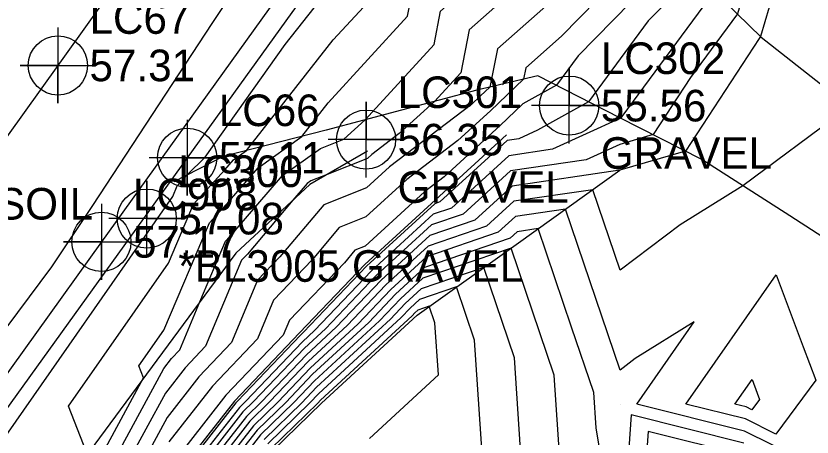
# Model space of a CAD drawing. Extents: x 2188792 to 2191981, y 386090 to 389710.
# Drawn here: x 2189752.4 to 2189815.5, y 387057.5 to 387090.8 of the extents above; entities that cross this region are included whole.
import ezdxf

# ---------------------------------------------------------------- set-up
doc = ezdxf.new("R2010")
doc.units = 0
for name, color, linetype in [('DTM Contours Major', 7, 'Continuous'), ('DTM Contours Minor', 7, 'Continuous'), ('Exist DTM QL2 LIDAR Elevation Point', 7, 'Continuous'), ('Exist Roads EOP', 7, 'Continuous'), ('Exist Roads EOP Cogo Elevation', 7, 'Continuous'), ('Exist Roads EOP Cogo Number', 7, 'Continuous'), ('Exist Roads EOP Cogo Point CELL', 7, 'Continuous'), ('Exist Roads EOT', 7, 'Continuous'), ('Exist Roads EOT Cogo Elevation', 7, 'Continuous'), ('Exist Roads EOT Cogo Number', 7, 'Continuous'), ('Exist Roads EOT Cogo Point CELL', 7, 'Continuous'), ('Exist Roads Soil Cogo Comment', 7, 'Continuous'), ('Exist Roads Soil Cogo Elevation', 7, 'Continuous'), ('Exist Roads Soil Cogo Number', 7, 'Continuous'), ('Exist Roads Soil Cogo Point CELL', 7, 'Continuous'), ('PH Exist DTM Breakline', 7, 'Continuous')]:
    doc.layers.add(name, color=color, linetype=linetype)

msp = doc.modelspace()

# ---------------------------------------------------------------- linework, layer by layer
at = {"layer": 'DTM Contours Major'}
for points in [[(2189750.977, 387056.76), (2189764.817, 387076.56), (2189765.17, 387077.392), (2189765.959, 387078.254), (2189767.371, 387079.663), (2189773.725, 387088.569), (2189777.916, 387093.909), (2189779.211, 387095.322), (2189779.288, 387095.712), (2189780.643, 387096.912), (2189782.512, 387099.089), (2189785.828, 387103.954), (2189796.579, 387119.177), (2189798.068, 387122.523), (2189798.475, 387123.446), (2189798.539, 387123.804), (2189808.292, 387137.215), (2189808.919, 387138.142), (2189809.222, 387138.615), (2189825.593, 387161.988)], [(2189818.014, 387135.578), (2189811.058, 387126.809), (2189810.786, 387125.379), (2189808.066, 387119.62), (2189806.017, 387115.841), (2189806.165, 387114.826), (2189804.371, 387109.683), (2189803.213, 387101.149), (2189803.472, 387100.716), (2189802.955, 387099.63), (2189799.965, 387096.58), (2189790.532, 387088.231), (2189789.941, 387085.204), (2189789.202, 387084.501), (2189788.475, 387083.836), (2189781.976, 387078.894), (2189780.172, 387077.246), (2189776.768, 387075.899), (2189773.29, 387071.764), (2189771.533, 387069.923), (2189769.466, 387064.988), (2189766.872, 387062.269), (2189764.365, 387059.07), (2189762.119, 387054.93)], [(2189818.839, 387129.976), (2189815.396, 387125.636), (2189814.426, 387120.529), (2189813.21, 387117.954), (2189812.294, 387116.264), (2189812.789, 387112.864), (2189811.979, 387110.541), (2189811.456, 387106.687), (2189814.112, 387102.255), (2189810.785, 387095.259), (2189809.534, 387091.004), (2189805.828, 387085.965), (2189802.864, 387081.443), (2189800.235, 387080.671), (2189797.567, 387079.45), (2189791.562, 387078.572), (2189787.825, 387075.156), (2189785.311, 387074.293), (2189780.928, 387070.288), (2189776.899, 387066.066), (2189775.243, 387064.539), (2189771.214, 387060.317), (2189770.37, 387059.498), (2189766.477, 387054.529)], [(2189795.488, 387055.37), (2189795.02, 387062.414), (2189791.607, 387072.471), (2189784.63, 387070.077), (2189782.841, 387068.441), (2189781.195, 387066.717), (2189776.043, 387061.965), (2189774.397, 387060.241), (2189771.771, 387057.69), (2189770.182, 387055.661)], [(2189809.984, 387056.073), (2189802.473, 387057.954), (2189801.923, 387050.273)]]:
    msp.add_lwpolyline(points, dxfattribs=at)
at = {"layer": 'DTM Contours Minor'}
for points in [[(2189757.992, 387056.32), (2189756.554, 387059.949), (2189764.468, 387071.271), (2189766.445, 387075.932), (2189768.945, 387078.662), (2189769.622, 387079.446), (2189770.648, 387080.179), (2189777.522, 387088.937), (2189781.313, 387093.073), (2189781.536, 387094.216), (2189785.504, 387097.728), (2189790.975, 387104.101), (2189798.548, 387115.211), (2189798.708, 387116.016), (2189799.145, 387116.599), (2189801.574, 387122.107), (2189802.082, 387124.936), (2189808.645, 387133.96), (2189811.25, 387137.817), (2189812.51, 387139.785), (2189824.983, 387157.591)], [(2189809.4, 387152.406), (2189801.396, 387139.864), (2189794.846, 387131.758), (2189788.146, 387120.877), (2189781.876, 387111.472), (2189771.155, 387095.136), (2189767.896, 387090.241), (2189758.451, 387075.833), (2189755.214, 387070.994), (2189740.876, 387051.783), (2189738.057, 387047.608), (2189727.447, 387033.342), (2189723.289, 387027.488), (2189710.113, 387008.133), (2189707.688, 387004.715), (2189696.068, 386987.603)], [(2189759.151, 387055.997), (2189762.508, 387062.186), (2189762.131, 387063.138), (2189764.119, 387065.982), (2189767.721, 387074.471), (2189769.273, 387076.167), (2189771.567, 387078.822), (2189775.039, 387081.303), (2189777.128, 387083.965), (2189783.415, 387090.825), (2189783.785, 387092.72), (2189790.365, 387098.543), (2189799.439, 387109.114), (2189800.025, 387109.974), (2189801.185, 387115.826), (2189804.36, 387120.058), (2189804.673, 387120.768), (2189805.625, 387126.067), (2189808.999, 387130.705), (2189813.581, 387137.493), (2189815.799, 387140.954)], [(2189760.14, 387055.641), (2189764.093, 387062.926), (2189764.718, 387063.724), (2189765.365, 387064.402), (2189766.961, 387068.213), (2189768.996, 387073.01), (2189769.602, 387073.672), (2189773.512, 387078.197), (2189776.52, 387080.347), (2189778.363, 387081.081), (2189780.054, 387082.615), (2189785.517, 387088.576), (2189786.034, 387091.223), (2189795.226, 387099.359), (2189800.987, 387106.07), (2189801.449, 387109.537), (2189803.322, 387115.057), (2189803.515, 387115.61), (2189803.506, 387115.672), (2189806.008, 387120.286), (2189809.104, 387126.842), (2189809.169, 387127.199), (2189809.352, 387127.451), (2189815.912, 387137.168)], [(2189818.179, 387134.458), (2189811.925, 387126.574), (2189811.514, 387124.409), (2189809.095, 387119.286), (2189807.273, 387115.926), (2189807.49, 387114.433), (2189805.893, 387109.854), (2189804.861, 387102.256), (2189805.6, 387101.024), (2189804.127, 387097.927), (2189795.604, 387089.233), (2189792.781, 387086.735), (2189792.604, 387085.829), (2189789.977, 387083.329), (2189787.395, 387080.969), (2189783.365, 387077.905), (2189780.115, 387074.935), (2189778.004, 387074.1), (2189775.847, 387071.536), (2189772.799, 387068.341), (2189771.517, 387065.281), (2189767.949, 387061.541), (2189764.501, 387057.141)], [(2189818.344, 387133.337), (2189812.793, 387126.34), (2189812.242, 387123.439), (2189810.124, 387118.953), (2189808.528, 387116.01), (2189808.814, 387114.041), (2189807.414, 387110.026), (2189806.51, 387103.364), (2189807.728, 387101.332), (2189805.299, 387096.224), (2189796.921, 387087.678), (2189795.204, 387085.349), (2189792.554, 387083.871), (2189790.753, 387082.158), (2189786.315, 387078.103), (2189784.754, 387076.915), (2189780.058, 387072.624), (2189779.24, 387072.3), (2189778.405, 387071.307), (2189774.064, 387066.759), (2189773.568, 387065.573), (2189769.026, 387060.814), (2189764.637, 387055.213)], [(2189818.509, 387132.217), (2189813.661, 387126.105), (2189812.97, 387122.469), (2189811.153, 387118.62), (2189809.783, 387116.095), (2189810.139, 387113.649), (2189808.936, 387110.198), (2189808.158, 387104.472), (2189809.856, 387101.64), (2189806.471, 387094.521), (2189802.47, 387090.439), (2189797.757, 387084.047), (2189793.715, 387081.793), (2189792.226, 387081.112), (2189791.293, 387080.975), (2189785.973, 387076.114), (2189785.583, 387075.98), (2189780.162, 387071.027), (2189775.18, 387065.806), (2189774.923, 387065.569), (2189769.941, 387060.348), (2189769.81, 387060.221), (2189764.996, 387054.076)], [(2189818.674, 387131.097), (2189814.528, 387125.871), (2189813.698, 387121.499), (2189812.181, 387118.287), (2189811.039, 387116.18), (2189811.464, 387113.256), (2189810.457, 387110.37), (2189809.807, 387105.58), (2189811.984, 387101.948), (2189807.799, 387093.145), (2189807.7, 387092.809), (2189800.397, 387082.878), (2189800.311, 387082.745), (2189800.233, 387082.723), (2189794.896, 387080.281), (2189791.428, 387079.773), (2189786.899, 387075.635), (2189785.447, 387075.137), (2189780.545, 387070.658), (2189776.04, 387065.936), (2189775.083, 387065.054), (2189770.577, 387060.333), (2189770.09, 387059.859), (2189765.736, 387054.303)], [(2189816.264, 387125.402), (2189815.154, 387119.559), (2189814.239, 387117.621), (2189813.55, 387116.349), (2189814.114, 387112.471), (2189813.5, 387110.713), (2189813.104, 387107.795), (2189816.24, 387102.563), (2189813.772, 387097.372), (2189811.367, 387089.198), (2189811.259, 387089.052), (2189805.417, 387080.141), (2189800.237, 387078.62), (2189791.697, 387077.37), (2189788.75, 387074.677), (2189785.174, 387073.45), (2189781.31, 387069.919), (2189777.758, 387066.197), (2189775.403, 387064.024), (2189771.851, 387060.302), (2189770.65, 387059.136), (2189767.218, 387054.755)], [(2189800.087, 387100.175), (2189788.283, 387089.727), (2189787.62, 387086.327), (2189785.553, 387084.073), (2189782.747, 387081.526), (2189780.587, 387079.884), (2189780.229, 387079.557), (2189777.044, 387078.296), (2189775.747, 387077.78), (2189775.457, 387077.573), (2189774.325, 387076.263), (2189770.732, 387071.992), (2189770.268, 387071.506), (2189767.416, 387064.695), (2189765.795, 387062.997), (2189764.229, 387060.998), (2189761.129, 387055.285)], [(2189817.868, 387083.253), (2189809.959, 387077.399), (2189804.997, 387074.311), (2189800.241, 387070.715), (2189798.08, 387077.083), (2189791.832, 387076.168), (2189789.676, 387074.198), (2189785.038, 387072.607), (2189781.693, 387069.549), (2189778.617, 387066.327), (2189775.563, 387063.51), (2189772.487, 387060.287), (2189770.931, 387058.774), (2189767.959, 387054.982)], [(2189814.472, 387055.803), (2189810.108, 387057.987), (2189801.564, 387060.127), (2189806.106, 387066.618), (2189801.449, 387063.722), (2189800.244, 387062.81), (2189795.922, 387075.546), (2189791.967, 387074.967), (2189790.602, 387073.719), (2189784.902, 387071.763), (2189782.075, 387069.18), (2189779.477, 387066.457), (2189775.723, 387062.995), (2189773.124, 387060.272), (2189771.211, 387058.413), (2189768.7, 387055.208)], [(2189799.705, 387050.126), (2189798.353, 387058.234), (2189798.167, 387061.036), (2189796.411, 387066.211), (2189793.764, 387074.008), (2189792.101, 387073.765), (2189791.527, 387073.241), (2189784.766, 387070.92), (2189782.458, 387068.811), (2189780.336, 387066.587), (2189775.883, 387062.48), (2189773.761, 387060.256), (2189771.491, 387058.051), (2189769.441, 387055.435)], [(2189792.623, 387052.505), (2189791.873, 387063.791), (2189789.449, 387070.934), (2189784.494, 387069.233), (2189783.223, 387068.072), (2189782.055, 387066.847), (2189776.202, 387061.45), (2189775.034, 387060.226), (2189772.051, 387057.328)], [(2189810.17, 387058.944), (2189805.449, 387060.127), (2189812.608, 387070.36), (2189814.756, 387064.65), (2189815.748, 387062.016), (2189812.581, 387057.737), (2189810.17, 387058.944)], [(2189789.608, 387051.909), (2189788.726, 387065.168), (2189787.291, 387069.397), (2189784.358, 387068.39), (2189783.606, 387067.702), (2189782.914, 387066.978), (2189776.362, 387060.935), (2189775.671, 387060.211), (2189772.332, 387056.967)], [(2189780.392, 387057.388), (2189785.853, 387062.425), (2189785.58, 387066.545), (2189785.134, 387067.86), (2189784.222, 387067.547), (2189783.988, 387067.333), (2189783.773, 387067.108), (2189776.522, 387060.42), (2189776.307, 387060.195), (2189772.612, 387056.605)], [(2189810.232, 387059.902), (2189809.333, 387060.127), (2189810.696, 387062.074), (2189811.104, 387060.987), (2189811.293, 387060.486), (2189810.691, 387059.672), (2189810.232, 387059.902)], [(2189810.046, 387057.03), (2189801.132, 387059.262), (2189800.479, 387050.146)]]:
    msp.add_lwpolyline(points, dxfattribs=at)
at = {"layer": 'Exist DTM QL2 LIDAR Elevation Point'}
for p, q in [((2189800.245, 387060.127), (2189800.245, 387060.127)), ((2189810.246, 387060.127), (2189810.246, 387060.127))]:
    msp.add_line(p, q, dxfattribs=at)
at = {"layer": 'Exist Roads EOP'}
msp.add_lwpolyline([(2190335.128, 387868.989), (2190306.373, 387829.271), (2190274.581, 387784.921), (2190245.133, 387744.071), (2190214.553, 387701.741), (2190184.89, 387660.475), (2190157.493, 387622.204), (2190126.048, 387578.501), (2190091.216, 387530.568), (2190059.634, 387486.726), (2190026.932, 387441.783), (2189997.689, 387401.032), (2189957.023, 387344.154), (2189927.908, 387303.922), (2189889.008, 387250.224), (2189856.606, 387205.5), (2189825.68, 387162.612), (2189795.668, 387120.822), (2189765.955, 387079.619), (2189734.998, 387036.704), (2189703.849, 386993.356), (2189673.984, 386951.979), (2189643.253, 386909.427)], dxfattribs=at)
at = {"layer": 'Exist Roads EOP Cogo Point CELL'}
msp.add_lwpolyline([(2189765.955, 387082.619), (2189765.955, 387076.619), (2189765.955, 387079.619), (2189768.955, 387079.619), (2189762.955, 387079.619)], dxfattribs=at)
msp.add_circle((2189765.955, 387079.619), 2.344, dxfattribs=at)
at = {"layer": 'Exist Roads EOT'}
for points in [[(2190174.375, 387667.889), (2190147.471, 387630.495), (2190115.247, 387585.778), (2190081.202, 387538.232), (2190049.502, 387494.256), (2190017.538, 387450.182), (2189987.334, 387408.357), (2189946.666, 387352.019), (2189917.402, 387311.129), (2189878.955, 387257.772), (2189846.565, 387212.819), (2189815.837, 387170.306), (2189785.374, 387128.351), (2189755.717, 387086.921), (2189724.953, 387044.041), (2189693.727, 387000.805), (2189663.933, 386959.217), (2189633.425, 386917.196)], [(2189989.253, 387391.986), (2189958.581, 387349.453), (2189928.09, 387307.216), (2189909.67, 387281.603), (2189884.44, 387246.513), (2189852.91, 387202.766), (2189821.507, 387159.305), (2189790.01, 387115.85), (2189759.16, 387072.957), (2189728.247, 387029.91), (2189696.407, 386985.689), (2189665.45, 386942.736), (2189635.049, 386900.502)]]:
    msp.add_lwpolyline(points, dxfattribs=at)
at = {"layer": 'Exist Roads EOT Cogo Point CELL'}
for points in [[(2189755.717, 387089.921), (2189755.717, 387083.921), (2189755.717, 387086.921), (2189752.717, 387086.921), (2189758.717, 387086.921)], [(2189759.16, 387075.957), (2189759.16, 387069.957), (2189759.16, 387072.957), (2189756.16, 387072.957), (2189762.16, 387072.957)]]:
    msp.add_lwpolyline(points, dxfattribs=at)
for centre in [(2189755.717, 387086.921), (2189759.16, 387072.957)]:
    msp.add_circle(centre, 2.344, dxfattribs=at)
at = {"layer": 'Exist Roads Soil Cogo Point CELL'}
for points in [[(2189796.22, 387080.739), (2189796.22, 387086.739), (2189796.22, 387083.739), (2189799.22, 387083.739), (2189793.22, 387083.739)], [(2189780.123, 387078.047), (2189780.123, 387084.047), (2189780.123, 387081.047), (2189783.123, 387081.047), (2189777.123, 387081.047)], [(2189762.751, 387071.797), (2189762.751, 387077.797), (2189762.751, 387074.797), (2189765.751, 387074.797), (2189759.751, 387074.797)]]:
    msp.add_lwpolyline(points, dxfattribs=at)
for centre in [(2189796.22, 387083.739), (2189780.123, 387081.047), (2189762.751, 387074.797)]:
    msp.add_circle(centre, 2.344, dxfattribs=at)
at = {"layer": 'PH Exist DTM Breakline'}
for points in [[(2189798.025, 387123.64), (2189798.312, 387116.047), (2189800.149, 387109.534), (2189802.322, 387100.55), (2189807.542, 387092.964), (2189811.422, 387089.144), (2189818.605, 387083.503)], [(2189820.636, 387070.546), (2189813.681, 387075.01), (2189806.726, 387079.473), (2189800.233, 387082.785), (2189793.741, 387086.096), (2189788.898, 387084.96), (2189776.955, 387081.794), (2189768.807, 387079.708), (2189764.892, 387077.71)], [(2189791.244, 387081.417), (2189785.633, 387076.29), (2189780.022, 387071.163), (2189774.864, 387065.758), (2189769.707, 387060.354), (2189764.723, 387053.993), (2189759.74, 387047.633), (2189754.442, 387040.492), (2189749.145, 387033.351), (2189743.848, 387026.211), (2189738.55, 387019.07), (2189733.253, 387011.929), (2189728.665, 387005.397), (2189724.078, 386998.864), (2189719.49, 386992.332), (2189714.902, 386985.799)], [(2189780.243, 387080.129), (2189775.664, 387077.506), (2189769.813, 387072.074), (2189764.002, 387064.208), (2189758.191, 387056.342), (2189753.421, 387049.372), (2189748.65, 387042.402), (2189743.88, 387035.432), (2189739.109, 387028.462), (2189733.563, 387020.597), (2189728.017, 387012.732), (2189722.471, 387004.866), (2189716.926, 386997.001), (2189711.359, 386989.34), (2189705.791, 386981.679), (2189700.224, 386974.018), (2189694.657, 386966.357)], [(2189733.024, 387005.524), (2189738.338, 387012.069), (2189744.34, 387018.96), (2189750.342, 387025.85), (2189756.188, 387033.049), (2189760.173, 387038.682), (2189764.158, 387044.315), (2189768.448, 387050.378), (2189772.738, 387056.442), (2189776.594, 387060.188), (2189784.161, 387067.166), (2189792.199, 387072.893), (2189800.237, 387078.62)]]:
    msp.add_lwpolyline(points, dxfattribs=at)

# ---------------------------------------------------------------- texts
at = {"layer": 'Exist Roads EOP Cogo Elevation'}
msp.add_text('57.11', height=2.5, dxfattribs=at).set_placement((2189768.455, 387078.369))
at = {"layer": 'Exist Roads EOP Cogo Number'}
msp.add_text('LC66', height=2.5, dxfattribs=at).set_placement((2189768.455, 387082.119))
at = {"layer": 'Exist Roads EOT Cogo Elevation'}
for s, p in [('57.31', (2189758.217, 387085.671)), ('57.17', (2189761.66, 387071.707))]:
    msp.add_text(s, height=2.5, dxfattribs=at).set_placement(p)
at = {"layer": 'Exist Roads EOT Cogo Number'}
for s, p in [('LC67', (2189758.217, 387089.421)), ('LC908', (2189761.66, 387075.457))]:
    msp.add_text(s, height=2.5, dxfattribs=at).set_placement(p)
at = {"layer": 'Exist Roads Soil Cogo Comment'}
for s, p in [('GRAVEL', (2189798.72, 387078.739)), ('GRAVEL', (2189782.623, 387076.047)), ('*BL3005 SOIL', (2189737.138, 387074.724)), ('*BL3005 GRAVEL', (2189765.251, 387069.797))]:
    msp.add_text(s, height=2.5, dxfattribs=at).set_placement(p)
at = {"layer": 'Exist Roads Soil Cogo Elevation'}
for s, p in [('55.56', (2189798.72, 387082.489)), ('56.35', (2189782.623, 387079.797)), ('57.08', (2189765.251, 387073.547))]:
    msp.add_text(s, height=2.5, dxfattribs=at).set_placement(p)
at = {"layer": 'Exist Roads Soil Cogo Number'}
for s, p in [('LC302', (2189798.72, 387086.239)), ('LC301', (2189782.623, 387083.547)), ('LC300', (2189765.251, 387077.297))]:
    msp.add_text(s, height=2.5, dxfattribs=at).set_placement(p)

doc.saveas('drawing.dxf')
